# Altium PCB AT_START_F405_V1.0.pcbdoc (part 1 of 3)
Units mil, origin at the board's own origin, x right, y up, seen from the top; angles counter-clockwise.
Board outline 15424.54 x 3535.36 mil, 2 copper layers (Top Layer, Bottom Layer); 147 components, 139 nets, 556 pads, 794 vias.
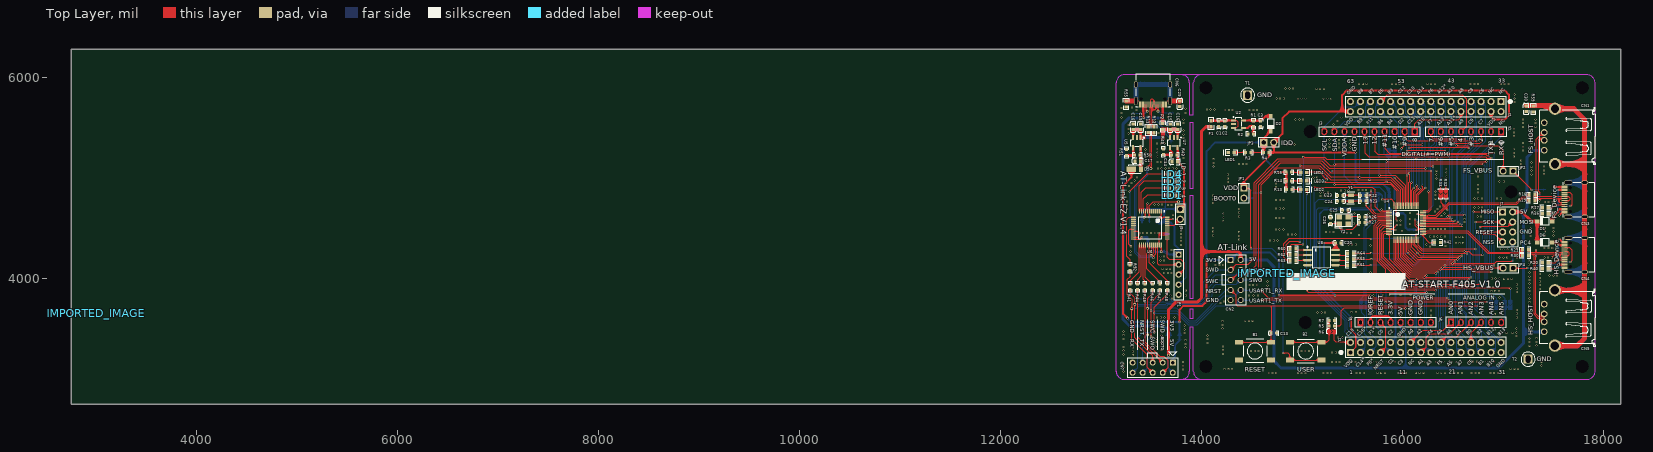
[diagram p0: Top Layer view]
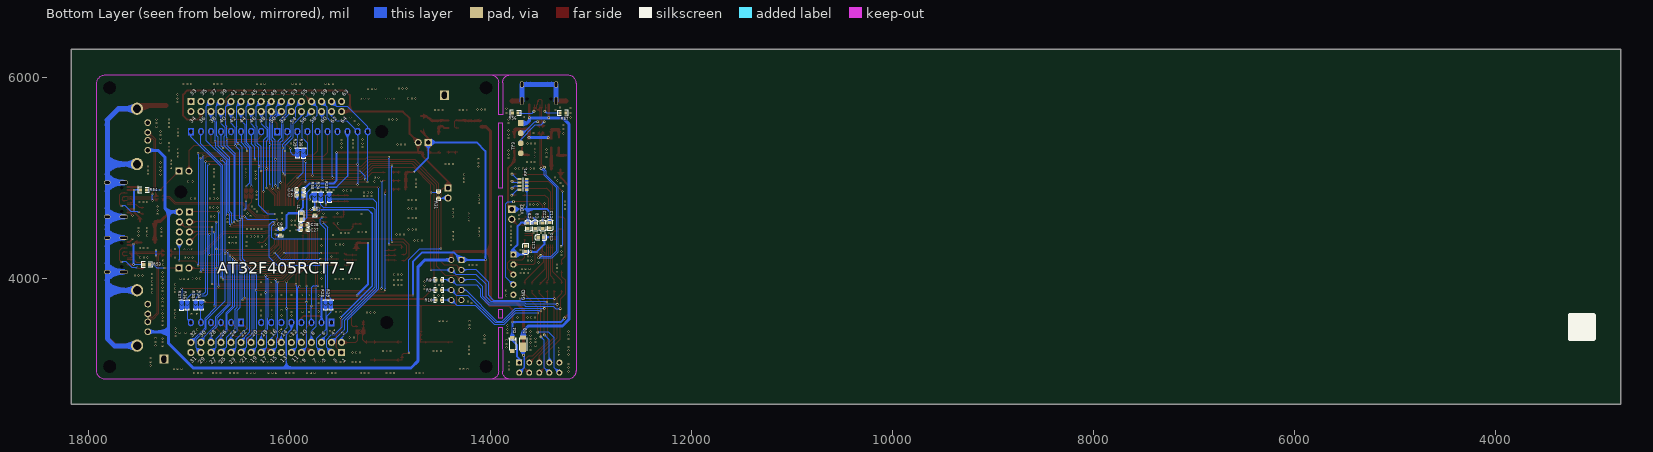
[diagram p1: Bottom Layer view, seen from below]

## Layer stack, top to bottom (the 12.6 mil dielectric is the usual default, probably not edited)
Top Layer: signal copper (thickness not stored)
Dielectric: dielectric 12.6, FR-4, Dk 4.8
Bottom Layer: signal copper (thickness not stored)

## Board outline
18174.54,2750 2750,2750 2750,6285.36 18174.54,6285.36
cut-out: 17855.2,5902.56 ccw(c17792.21,5902.56) 17729.21,5902.56 ccw(c17792.21,5902.56)
cut-out: 17854.57,3127.57 ccw(c17791.58,3127.57) 17728.58,3127.57 ccw(c17791.58,3127.57)
cut-out: 14107.57,3127.57 ccw(c14044.58,3127.57) 13981.58,3127.57 ccw(c14044.58,3127.57)
cut-out: 14107.57,5902.56 ccw(c14044.58,5902.56) 13981.58,5902.56 ccw(c14044.58,5902.56)
cut-out: 17146.57,4865.56 ccw(c17083.58,4865.56) 17020.58,4865.56 ccw(c17083.58,4865.56)
cut-out: 15096.57,3565.57 ccw(c15033.58,3565.57) 14970.58,3565.57 ccw(c15033.58,3565.57)
cut-out: 15146.57,5465.56 ccw(c15083.58,5465.56) 15020.58,5465.56 ccw(c15083.58,5465.56)

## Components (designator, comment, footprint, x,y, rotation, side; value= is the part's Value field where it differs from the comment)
B1 "BUTTON_SMT,6.0x6.0x4.5mm" BUTTON_SMT_6*6*5 14533.58,3280.57 r0 top
B2 "BUTTON_SMT,6.0x6.0x4.5mm" BUTTON_SMT_6*6*5 15038.58,3280.57 r180 top
C1 "10uF" 0603_C-M 14172.58,5544.37 r90 top
C2 "0.1uF" 0603_C-M 14232.58,5544.37 r90 top
C3 "10uF" 0603_C-M 14590.58,5544.37 r90 top
C4 "4.7uF" 0603_C-M 15896.58,4883.56 r180 bottom
C5 "0.1uF" 0603_C-M 15897.08,4833.56 r180 bottom
C6 "0.1uF" 0603_C-M 16091.58,4461.56 r90 bottom
C7 "0.1uF" 0603_C-M 15750.58,4662.56 r90 bottom
C8 "4.7uF" C0603 13556.58,4527.56 r270 bottom
C9 "CC0603KRX7R9BB104" C0603 13628.58,4527.56 r270 bottom
C10 "CC0603KRX7R9BB104" C0603 13498.58,4411.56 r0 bottom
C11 "CC0603KRX7R9BB104" C0603 13650.58,4299.56 r90 bottom
C12 "CC0603KRX7R9BB104" C0603 13410.58,4533.56 r270 bottom
C13 "0.1uF" 0603_C-M 14720.58,3459.57 r0 top
C14 "CL10A106KP8NNNC" C0603 13736.58,5164.56 r180 top
C15 "CL10A106KP8NNNC" C0603 13689.58,5514.56 r90 top
C16 "CC0603KRX7R9BB104" C0603 13764.58,5514.12 r90 top
C17 "CL10A106KP8NNNC" C0603 13367.58,5172.56 r180 top
C18 "CL10A106KP8NNNC" C0603 13319.58,5513.56 r90 top
C19 "CC0603KRX7R9BB104" C0603 13395.58,5513.12 r90 top
C20 "0.1uF" 0603_C-M 15363.02,4357 r0 top
C22 "CC0603KRX7R9BB104" C0603 13480.58,4529.56 r270 bottom
C23 "18pF" 0603_C-M 15383.58,4831.56 r180 top
C24 "18pF" 0603_C-M 15383.58,4772.56 r180 top
C25 "15pF" 0603_C-M 15433.08,4683.56 r180 top
C26 "15pF" 0603_C-M 15283.58,4576.06 r90 top
C27 "1uF" 0603_C-M 15857.08,4487.56 r180 bottom
C28 "0.1uF" 0603_C-M 15857.08,4536.56 r180 bottom
C29 "CC0603KRX7R9BB104" C0603 13784.58,5742.56 r90 top
C30 "CC0603KRX7R9BB104" C0603 17232.58,5692.01 r90 top
CN1 "USB type A" USB-A-TH__USB-AF-90 17466.58,5417.56 r90 top
CN2 "NC(Header 2x5)" HDR2X5#1 14290.92,4188.85 r270 top
CN3 "TYPEC-304-BCP16" USB-C-SMD_TYPEC-304-BCP16#1 17715.58,4788.56 r90 top
CN4 "TYPEC-304-BCP16" USB-C-SMD_TYPEC-304-BCP16#1 17715.58,4238.56 r90 top
CN5 "USB type A" USB-A-TH__USB-AF-90 17465.58,3610.57 r90 top
CN6 "TYPEC-304-BCP16" USB-C-SMD_TYPEC-304-BCP16#2 13518.58,5834.56 r180 top
CN7 "CON1" HDR2X5#2 13715.38,3165.97 r180 top
D1 "DFLS130L-7" SOD-123 17417.58,4572.56 r0 top
D2 "DFLS130L-7" SOD-123 14690.58,5544.36 r90 top
D3 "DFLS130L-7" POWERDI-123_L2.8-W1.8-LS3.7-RD 13676.62,3367.57 r90 bottom
D4 "SMF3.3A" SOD-123_L2.8-W1.8-LS3.7-RD 13782.58,3347.57 r270 bottom
D5 "DFLS130L-7" POWERDI-123_L2.8-W1.8-LS3.7-RD 13350.58,5090.56 r0 top
D6 "DFLS130L-7" SOD-123 17417.58,4363.56 r0 top
F1 "SMD0603B050TF" R0603#1 14096.58,5513.86 r90 top
F2 "SMD0603B050TF" R0603#2 13616.58,5517.56 r270 top
IMPORTED_IMAGE "IMPORTED_IMAGE" IMPORTED_IMAGE 3000,3658.57 r0 top
IMPORTED_IMAGE "IMPORTED_IMAGE" IMPORTED_IMAGE 14848.52,4055 r0 top
J1 "Header 2x16" HDR-M-2.54_2X16 16233.44,5714.86 r180 top
J2 "Header 2x16" HDR-M-2.54_2X16 16233.88,3317.14 r0 top
J3 "CON10" "FEMALE HEADER 1X10" 16123.87,5465.56 r180 top
J4 "CON8" "FEMALE HEADER 1X8" 15583.87,3565.56 r0 top
J5 "CON8" "FEMALE HEADER 1X8" 16983.87,5465.56 r180 top
J6 "CON6" "FEMALE HEADER 1X6" 16483.87,3565.57 r0 top
J7 "Header 4X2" HDR2X4 16998.88,4666.16 r270 top
J9 "1X2P,Male,DIP_2.54" HDR1X2 13789.38,4692.97 r270 top
JP1 "NC(Header 1x2)" "HEADER 1X2" 14423.58,4903.56 r270 top
JP2 "NC(Header 1x2)" "HEADER 1X2" 17103.58,5072.56 r180 top
JP3 "NC(Header 1x2)" "HEADER 1X2" 14620.58,5357.56 r0 top
JP4 "NC(Header 1x2)" "HEADER 1X2" 17103.58,4107.56 r180 top
L1 "0.5A,600R@100Mhz" 0603_L 15884.58,4622.56 r270 bottom
LD1 "RED" LED0603 13742.58,4832.77 r180 top
LD2 "GREEN" LED0603 13742.58,4902.37 r180 top
LD3 "BLUE" LED0603 13742.58,4971.97 r180 top
LD4 "YELLOW" LED0603 13742.58,5041.56 r180 top
LED1 "RED" LED0603 14328.58,5258.56 r180 top
LED2 "RED" LED0603 14988.58,4889.56 r0 top
LED3 "YELLOW" LED0603 14988.58,4975.56 r0 top
LED4 "GREEN" LED0603 14988.58,5059.56 r0 top
P1 "HDR-M-2.54_1x5" HDR-M-2.54_1X5 13772.58,4041.57 r270 top
R1 "51k" 0603_R-M 14518.58,5544.37 r270 top
R2 "15k" 0603_R-M 14490.58,5443.56 r180 top
R3 "1K" 0603_R-M 14466.58,5258.56 r0 top
R4 "0R" 0603_R-M 14647.58,5257.56 r0 top
R5 "0R" 0603_R-M 15296.58,3529.57 r0 top
R6 "NC" SB-PAD 15296.58,3473.57 r0 top
R7 "100K" 0603_R-M 15296.58,3585.57 r180 top
R8 "470R" 0603_R-M 14518.27,3989.76 r0 bottom
R9 "470R" 0603_R-M 14518.27,3887.76 r0 bottom
R10 "470R" 0603_R-M 14518.27,3789.76 r0 bottom
R11 "0603WAF0000T5E" R0603#2 13469.58,5484.9 r270 top
R12 "0603WAF0000T5E" R0603#2 13528.58,5484.56 r270 top
R13 "1K" 0603_R-M 14872.58,4889.56 r0 top
R14 "1K" 0603_R-M 14871.19,4975.21 r0 top
R15 "1K" 0603_R-M 14871.19,5061.21 r0 top
R16 "0603WAF5101T5E" R0603#2 17423.58,4646.56 r180 top
R17 "0603WAF5101T5E" R0603#2 17422.58,4706.56 r180 top
R18 "0603WAF220JT5E" R0603#2 17291.92,4837.56 r0 top
R19 "0603WAF220JT5E" R0603#2 17291.58,4778.56 r0 top
R20 "0603WAF5101T5E" R0603#2 17423.58,4160.56 r180 top
R21 "0603WAF220JT5E" R0603#2 17225.92,4287.56 r0 top
R22 "0R" 0603_R-M 15609.58,4831.56 r0 top
R23 "0R" 0603_R-M 15611.58,4773.56 r0 top
R24 "NC" SB-PAD 15689.58,4814.56 r270 bottom
R25 "NC" SB-PAD 15605.58,4814.56 r270 bottom
R26 "0R" 0603_R-M 15600.58,4615.56 r0 top
R27 "0R" 0603_R-M 15600.58,4561.56 r0 top
R28 "NC" SB-PAD 15643.58,3741.57 r270 bottom
R29 "NC" SB-PAD 15589.58,3742.57 r270 bottom
R30 "0603WAF220JT5E" R0603#2 17225.92,4228.56 r0 top
R31 "10K" 0603_R-M 14519.52,4831 r270 bottom
R32 "NC" SB-PAD 16433.58,4847.44 r270 top
R33 "NC" SB-PAD 16380.58,4847.85 r270 top
R34 "0R" SB-PAD 16880.58,3741.45 r270 bottom
R35 "NC" SB-PAD 16936.58,3740.96 r270 bottom
R36 "NC" SB-PAD 17020.58,3740.45 r270 bottom
R37 "0R" SB-PAD 17076.58,3739.84 r270 bottom
R38 "NC" SB-PAD 15864.58,5252.93 r270 bottom
R39 "0R" SB-PAD 15924.58,5253.56 r270 bottom
R40 "0603WAF5101T5E" R0603#2 17422.92,4100.56 r180 top
R41 "33R" 0603_R-M 13290.58,3919.57 r270 top
R42 "0603WAD1202T5E" R0603#2 16350.27,4361.56 r0 top
R43 "47K" 0603_R-M 13730.42,5235.02 r180 top
R44 "33R" 0603_R-M 13364.58,3919.57 r270 top
R45 "33R" 0603_R-M 13436.58,3919.57 r270 top
R46 "33R" 0603_R-M 13514.58,3921.57 r270 top
R47 "33R" 0603_R-M 13586.58,3923.57 r270 top
R48 "33R" 0603_R-M 13660.58,3919.57 r270 top
R49 "15K" 0603_R-M 13620.58,5263.56 r270 top
R50 "51K" 0603_R-M 13362.58,5232.56 r180 top
R51 "15K" 0603_R-M 13254.58,5257.56 r270 top
R52 "33R" 0603_R-M 13288.58,4109.56 r270 top
R53 "0603WAF1002T5E" R0603#2 17422.58,4141.56 r0 bottom
R54 "0603WAF1002T5E" R0603#2 17455.92,4884.56 r0 bottom
R55 "RC0603FR-071ML" R0603#2 13250.58,5740.9 r270 top
R56 "0603WAF5101T5E" R0603#2 13755.58,5650.56 r0 bottom
R57 "0603WAF5101T5E" R0603#2 13279.58,5650.56 r180 bottom
R58 "0R" SB-PAD 15750.58,4816.56 r270 bottom
R59 "RC0603FR-071ML" R0603#2 17302.58,5690.9 r270 top
R60 "0603WAF330JT5E" R0603#2 14911.86,4299 r0 top
R61 "0603WAF330JT5E" R0603#2 15484.18,4136 r180 top
R62 "0603WAF330JT5E" R0603#2 14911.86,4239 r0 top
R63 "0603WAF330JT5E" R0603#2 14911.86,4180 r0 top
R64 "0603WAF330JT5E" R0603#2 15484.18,4255 r180 top
R65 "0603WAF330JT5E" R0603#2 15484.18,4195.5 r180 top
RP1 "1K" 0603*4,8P4R 13640.58,4886.56 r90 bottom
T1 "Testpoint" TESTHOOK 14460.58,5827.56 r270 top
T2 "Testpoint" TESTHOOK 17252.58,3200.57 r90 top
TP3 "1X4P_2.54F" "HDR1X4 - TOP" 13699.93,5550.02 r90 bottom
U2 "RT9080N-08GJ5" SOT-23-5 14382.58,5476.54 r0 top
U4 "AT32F405RCT7-7" IC_LQFP64_7X7 16037.58,4558.56 r0 top
U5 "RT9080N-08GJ5" SOT-23-5 13295.14,5339.91 r270 top
U6 "AT32F403ACCT7" "LQFP48 - 2" 13600.09,4672.02 r270 top
U7 "RT9080N-08GJ5" SOT-23-5 13664.35,5341.91 r270 top
U8 "EN25QH128A-104HIP2T" SOP-8_L5.3-W5.3-P1.27-LS8.0-BL 15195.52,4212 r270 top
Y1 "32.768KHz" "XTAL_SOP - FC-12M" 15487.58,4831.56 r270 top
Y2 "CJ13-120001210B20" CRYSTAL-SMD_4P-L3.2-W2.5-BL 15416.58,4582.56 r0 top

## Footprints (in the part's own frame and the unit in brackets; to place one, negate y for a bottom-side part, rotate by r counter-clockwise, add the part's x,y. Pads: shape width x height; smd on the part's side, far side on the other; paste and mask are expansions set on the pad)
0603*4,8P4R [mm]
  rect 0.55x0.95 smd paste+0 mask+0.102: 1(0,0) 4(2.7,0) 5(2.7,1.85) 8(0,1.85)
  rect 0.5x0.95 smd paste+0 mask+0.102: 2(0.9,0) 3(1.8,0) 6(1.8,1.85) 7(0.9,1.85)
  silkscreen extent -0.43,0.94 3.1,0.94
0603_C-M [mil]
  rect 30x30 smd paste+0 mask+4: 1(27.5,0) 2(-27.5,0)
  silkscreen extent -50,-21 50,21
0603_L [mm]
  rect 0.93x0.9 smd paste+0 mask+0.102: 1(-0.77,0) 2(0.77,0)
  silkscreen extent -1.4,-0.64 1.4,0.64
0603_R-M [mil]
  rect 30x30 smd paste+0 mask+4: 1(27.5,0) 2(-27.5,0)
  silkscreen extent -50,-21 50,21
BUTTON_SMT_6*6*5 [mm]
  rect 2x1.2 smd paste+0 mask+0.102: 1(-4,2.25) 2(4,2.25) 3(-4,-2.25) 4(4,-2.25)
  silkscreen extent -3,-3 3,3
C0603 [mm]
  rect 0.8x0.9 smd paste+0 mask+0.051: 1(-0.7,0) 2(0.7,0)
  silkscreen extent -1.41,-0.71 1.39,0.72
CRYSTAL-SMD_4P-L3.2-W2.5-BL [mm]
  rect 1.4x1.2 smd paste+0 mask+0.051: 1(-1.1,-0.85) 2(1.1,-0.85) 3(1.1,0.85) 4(-1.1,0.85)
  silkscreen extent -2.26,-1.91 2.03,1.68
"FEMALE HEADER 1X6" [mm]
  oval 1x0.7 hole 0.7 slot 1 at 90 deg: 1(0,0) 2(2.54,0) 3(5.08,0) 4(7.62,0) 5(10.16,0) 6(12.7,0)
  Top Layer region: 13.4,-0.2 13.306,-0.55 13.05,-0.806 12.7,-0.9 12.35,-0.806 12.094,-0.55 12,-0.2 12,0.2 12.094,0.55 12.35,0.806 12.7,0.9 13.05,0.806 13.306,0.55 13.4,0.2
  Top Layer region: 10.86,-0.2 10.766,-0.55 10.51,-0.806 10.16,-0.9 9.81,-0.806 9.554,-0.55 9.46,-0.2 9.46,0.2 9.554,0.55 9.81,0.806 10.16,0.9 10.51,0.806 10.766,0.55 10.86,0.2
  Top Layer region: 8.32,-0.2 8.226,-0.55 7.97,-0.806 7.62,-0.9 7.27,-0.806 7.014,-0.55 6.92,-0.2 6.92,0.2 7.014,0.55 7.27,0.806 7.62,0.9 7.97,0.806 8.226,0.55 8.32,0.2
  Top Layer region: 5.78,-0.2 5.686,-0.55 5.43,-0.806 5.08,-0.9 4.73,-0.806 4.474,-0.55 4.38,-0.2 4.38,0.2 4.474,0.55 4.73,0.806 5.08,0.9 5.43,0.806 5.686,0.55 5.78,0.2
  Top Layer region: 3.24,-0.2 3.146,-0.55 2.89,-0.806 2.54,-0.9 2.19,-0.806 1.934,-0.55 1.84,-0.2 1.84,0.2 1.934,0.55 2.19,0.806 2.54,0.9 2.89,0.806 3.146,0.55 3.24,0.2
  Top Layer region: -0.7,0.9 0.7,0.9 0.7,-0.9 -0.7,-0.9
  Bottom Layer region: 13.4,-0.2 13.306,-0.55 13.05,-0.806 12.7,-0.9 12.35,-0.806 12.094,-0.55 12,-0.2 12,0.2 12.094,0.55 12.35,0.806 12.7,0.9 13.05,0.806 13.306,0.55 13.4,0.2
  Bottom Layer region: 10.86,-0.2 10.766,-0.55 10.51,-0.806 10.16,-0.9 9.81,-0.806 9.554,-0.55 9.46,-0.2 9.46,0.2 9.554,0.55 9.81,0.806 10.16,0.9 10.51,0.806 10.766,0.55 10.86,0.2
  Bottom Layer region: 8.32,-0.2 8.226,-0.55 7.97,-0.806 7.62,-0.9 7.27,-0.806 7.014,-0.55 6.92,-0.2 6.92,0.2 7.014,0.55 7.27,0.806 7.62,0.9 7.97,0.806 8.226,0.55 8.32,0.2
  Bottom Layer region: 5.78,-0.2 5.686,-0.55 5.43,-0.806 5.08,-0.9 4.73,-0.806 4.474,-0.55 4.38,-0.2 4.38,0.2 4.474,0.55 4.73,0.806 5.08,0.9 5.43,0.806 5.686,0.55 5.78,0.2
  Bottom Layer region: 3.24,-0.2 3.146,-0.55 2.89,-0.806 2.54,-0.9 2.19,-0.806 1.934,-0.55 1.84,-0.2 1.84,0.2 1.934,0.55 2.19,0.806 2.54,0.9 2.89,0.806 3.146,0.55 3.24,0.2
  Bottom Layer region: -0.7,0.9 0.7,0.9 0.7,-0.9 -0.7,-0.9
  Multi-Layer region: 13.4,-0.2 13.306,-0.55 13.05,-0.806 12.7,-0.9 12.35,-0.806 12.094,-0.55 12,-0.2 12,0.2 12.094,0.55 12.35,0.806 12.7,0.9 13.05,0.806 13.306,0.55 13.4,0.2
  Multi-Layer region: 10.86,-0.2 10.766,-0.55 10.51,-0.806 10.16,-0.9 9.81,-0.806 9.554,-0.55 9.46,-0.2 9.46,0.2 9.554,0.55 9.81,0.806 10.16,0.9 10.51,0.806 10.766,0.55 10.86,0.2
  Multi-Layer region: 8.32,-0.2 8.226,-0.55 7.97,-0.806 7.62,-0.9 7.27,-0.806 7.014,-0.55 6.92,-0.2 6.92,0.2 7.014,0.55 7.27,0.806 7.62,0.9 7.97,0.806 8.226,0.55 8.32,0.2
  Multi-Layer region: 5.78,-0.2 5.686,-0.55 5.43,-0.806 5.08,-0.9 4.73,-0.806 4.474,-0.55 4.38,-0.2 4.38,0.2 4.474,0.55 4.73,0.806 5.08,0.9 5.43,0.806 5.686,0.55 5.78,0.2
  Multi-Layer region: 3.24,-0.2 3.146,-0.55 2.89,-0.806 2.54,-0.9 2.19,-0.806 1.934,-0.55 1.84,-0.2 1.84,0.2 1.934,0.55 2.19,0.806 2.54,0.9 2.89,0.806 3.146,0.55 3.24,0.2
  Multi-Layer region: -0.7,0.9 0.7,0.9 0.7,-0.9 -0.7,-0.9
  silkscreen extent -1.27,-1.17 13.97,1.27
"FEMALE HEADER 1X8" [mm]
  oval 1x0.7 hole 0.7 slot 1 at 90 deg: 1(0,0) 2(2.54,0) 3(5.08,0) 4(7.62,0) 5(10.16,0) 6(12.7,0) 7(15.24,0) 8(17.78,0)
  Top Layer region: -0.7,0.9 0.7,0.9 0.7,-0.9 -0.7,-0.9
  Top Layer region: 3.24,-0.2 3.146,-0.55 2.89,-0.806 2.54,-0.9 2.19,-0.806 1.934,-0.55 1.84,-0.2 1.84,0.2 1.934,0.55 2.19,0.806 2.54,0.9 2.89,0.806 3.146,0.55 3.24,0.2
  Top Layer region: 5.78,-0.2 5.686,-0.55 5.43,-0.806 5.08,-0.9 4.73,-0.806 4.474,-0.55 4.38,-0.2 4.38,0.2 4.474,0.55 4.73,0.806 5.08,0.9 5.43,0.806 5.686,0.55 5.78,0.2
  Top Layer region: 8.32,-0.2 8.226,-0.55 7.97,-0.806 7.62,-0.9 7.27,-0.806 7.014,-0.55 6.92,-0.2 6.92,0.2 7.014,0.55 7.27,0.806 7.62,0.9 7.97,0.806 8.226,0.55 8.32,0.2
  Top Layer region: 10.86,-0.2 10.766,-0.55 10.51,-0.806 10.16,-0.9 9.81,-0.806 9.554,-0.55 9.46,-0.2 9.46,0.2 9.554,0.55 9.81,0.806 10.16,0.9 10.51,0.806 10.766,0.55 10.86,0.2
  Top Layer region: 13.4,-0.2 13.306,-0.55 13.05,-0.806 12.7,-0.9 12.35,-0.806 12.094,-0.55 12,-0.2 12,0.2 12.094,0.55 12.35,0.806 12.7,0.9 13.05,0.806 13.306,0.55 13.4,0.2
  Top Layer region: 15.94,-0.2 15.846,-0.55 15.59,-0.806 15.24,-0.9 14.89,-0.806 14.634,-0.55 14.54,-0.2 14.54,0.2 14.634,0.55 14.89,0.806 15.24,0.9 15.59,0.806 15.846,0.55 15.94,0.2
  Top Layer region: 18.48,-0.2 18.386,-0.55 18.13,-0.806 17.78,-0.9 17.43,-0.806 17.174,-0.55 17.08,-0.2 17.08,0.2 17.174,0.55 17.43,0.806 17.78,0.9 18.13,0.806 18.386,0.55 18.48,0.2
  Bottom Layer region: -0.7,0.9 0.7,0.9 0.7,-0.9 -0.7,-0.9
  Bottom Layer region: 3.24,-0.2 3.146,-0.55 2.89,-0.806 2.54,-0.9 2.19,-0.806 1.934,-0.55 1.84,-0.2 1.84,0.2 1.934,0.55 2.19,0.806 2.54,0.9 2.89,0.806 3.146,0.55 3.24,0.2
  Bottom Layer region: 5.78,-0.2 5.686,-0.55 5.43,-0.806 5.08,-0.9 4.73,-0.806 4.474,-0.55 4.38,-0.2 4.38,0.2 4.474,0.55 4.73,0.806 5.08,0.9 5.43,0.806 5.686,0.55 5.78,0.2
  Bottom Layer region: 8.32,-0.2 8.226,-0.55 7.97,-0.806 7.62,-0.9 7.27,-0.806 7.014,-0.55 6.92,-0.2 6.92,0.2 7.014,0.55 7.27,0.806 7.62,0.9 7.97,0.806 8.226,0.55 8.32,0.2
  Bottom Layer region: 10.86,-0.2 10.766,-0.55 10.51,-0.806 10.16,-0.9 9.81,-0.806 9.554,-0.55 9.46,-0.2 9.46,0.2 9.554,0.55 9.81,0.806 10.16,0.9 10.51,0.806 10.766,0.55 10.86,0.2
  Bottom Layer region: 13.4,-0.2 13.306,-0.55 13.05,-0.806 12.7,-0.9 12.35,-0.806 12.094,-0.55 12,-0.2 12,0.2 12.094,0.55 12.35,0.806 12.7,0.9 13.05,0.806 13.306,0.55 13.4,0.2
  Bottom Layer region: 15.94,-0.2 15.846,-0.55 15.59,-0.806 15.24,-0.9 14.89,-0.806 14.634,-0.55 14.54,-0.2 14.54,0.2 14.634,0.55 14.89,0.806 15.24,0.9 15.59,0.806 15.846,0.55 15.94,0.2
  Bottom Layer region: 18.48,-0.2 18.386,-0.55 18.13,-0.806 17.78,-0.9 17.43,-0.806 17.174,-0.55 17.08,-0.2 17.08,0.2 17.174,0.55 17.43,0.806 17.78,0.9 18.13,0.806 18.386,0.55 18.48,0.2
  Multi-Layer region: -0.7,0.9 0.7,0.9 0.7,-0.9 -0.7,-0.9
  Multi-Layer region: 3.24,-0.2 3.146,-0.55 2.89,-0.806 2.54,-0.9 2.19,-0.806 1.934,-0.55 1.84,-0.2 1.84,0.2 1.934,0.55 2.19,0.806 2.54,0.9 2.89,0.806 3.146,0.55 3.24,0.2
  Multi-Layer region: 5.78,-0.2 5.686,-0.55 5.43,-0.806 5.08,-0.9 4.73,-0.806 4.474,-0.55 4.38,-0.2 4.38,0.2 4.474,0.55 4.73,0.806 5.08,0.9 5.43,0.806 5.686,0.55 5.78,0.2
  Multi-Layer region: 8.32,-0.2 8.226,-0.55 7.97,-0.806 7.62,-0.9 7.27,-0.806 7.014,-0.55 6.92,-0.2 6.92,0.2 7.014,0.55 7.27,0.806 7.62,0.9 7.97,0.806 8.226,0.55 8.32,0.2
  Multi-Layer region: 10.86,-0.2 10.766,-0.55 10.51,-0.806 10.16,-0.9 9.81,-0.806 9.554,-0.55 9.46,-0.2 9.46,0.2 9.554,0.55 9.81,0.806 10.16,0.9 10.51,0.806 10.766,0.55 10.86,0.2
  Multi-Layer region: 13.4,-0.2 13.306,-0.55 13.05,-0.806 12.7,-0.9 12.35,-0.806 12.094,-0.55 12,-0.2 12,0.2 12.094,0.55 12.35,0.806 12.7,0.9 13.05,0.806 13.306,0.55 13.4,0.2
  Multi-Layer region: 15.94,-0.2 15.846,-0.55 15.59,-0.806 15.24,-0.9 14.89,-0.806 14.634,-0.55 14.54,-0.2 14.54,0.2 14.634,0.55 14.89,0.806 15.24,0.9 15.59,0.806 15.846,0.55 15.94,0.2
  Multi-Layer region: 18.48,-0.2 18.386,-0.55 18.13,-0.806 17.78,-0.9 17.43,-0.806 17.174,-0.55 17.08,-0.2 17.08,0.2 17.174,0.55 17.43,0.806 17.78,0.9 18.13,0.806 18.386,0.55 18.48,0.2
  silkscreen extent -1.27,-1.17 19.05,1.27
"FEMALE HEADER 1X10" [mm]
  oval 1x0.7 hole 0.7 slot 1 at 90 deg: 1(0,0) 2(2.54,0) 3(5.08,0) 4(7.62,0) 5(10.16,0) 6(12.7,0) 7(15.24,0) 8(17.78,0) 9(20.32,0) 10(22.86,0)
  Top Layer region: 23.56,-0.2 23.466,-0.55 23.21,-0.806 22.86,-0.9 22.51,-0.806 22.254,-0.55 22.16,-0.2 22.16,0.2 22.254,0.55 22.51,0.806 22.86,0.9 23.21,0.806 23.466,0.55 23.56,0.2
  Top Layer region: 21.02,-0.2 20.926,-0.55 20.67,-0.806 20.32,-0.9 19.97,-0.806 19.714,-0.55 19.62,-0.2 19.62,0.2 19.714,0.55 19.97,0.806 20.32,0.9 20.67,0.806 20.926,0.55 21.02,0.2
  Top Layer region: 18.48,-0.2 18.386,-0.55 18.13,-0.806 17.78,-0.9 17.43,-0.806 17.174,-0.55 17.08,-0.2 17.08,0.2 17.174,0.55 17.43,0.806 17.78,0.9 18.13,0.806 18.386,0.55 18.48,0.2
  Top Layer region: 15.94,-0.2 15.846,-0.55 15.59,-0.806 15.24,-0.9 14.89,-0.806 14.634,-0.55 14.54,-0.2 14.54,0.2 14.634,0.55 14.89,0.806 15.24,0.9 15.59,0.806 15.846,0.55 15.94,0.2
  Top Layer region: 13.4,-0.2 13.306,-0.55 13.05,-0.806 12.7,-0.9 12.35,-0.806 12.094,-0.55 12,-0.2 12,0.2 12.094,0.55 12.35,0.806 12.7,0.9 13.05,0.806 13.306,0.55 13.4,0.2
  Top Layer region: 10.86,-0.2 10.766,-0.55 10.51,-0.806 10.16,-0.9 9.81,-0.806 9.554,-0.55 9.46,-0.2 9.46,0.2 9.554,0.55 9.81,0.806 10.16,0.9 10.51,0.806 10.766,0.55 10.86,0.2
  Top Layer region: 8.32,-0.2 8.226,-0.55 7.97,-0.806 7.62,-0.9 7.27,-0.806 7.014,-0.55 6.92,-0.2 6.92,0.2 7.014,0.55 7.27,0.806 7.62,0.9 7.97,0.806 8.226,0.55 8.32,0.2
  Top Layer region: 5.78,-0.2 5.686,-0.55 5.43,-0.806 5.08,-0.9 4.73,-0.806 4.474,-0.55 4.38,-0.2 4.38,0.2 4.474,0.55 4.73,0.806 5.08,0.9 5.43,0.806 5.686,0.55 5.78,0.2
  Top Layer region: 3.24,-0.2 3.146,-0.55 2.89,-0.806 2.54,-0.9 2.19,-0.806 1.934,-0.55 1.84,-0.2 1.84,0.2 1.934,0.55 2.19,0.806 2.54,0.9 2.89,0.806 3.146,0.55 3.24,0.2
  Top Layer region: -0.7,0.9 0.7,0.9 0.7,-0.9 -0.7,-0.9
  Bottom Layer region: 23.56,-0.2 23.466,-0.55 23.21,-0.806 22.86,-0.9 22.51,-0.806 22.254,-0.55 22.16,-0.2 22.16,0.2 22.254,0.55 22.51,0.806 22.86,0.9 23.21,0.806 23.466,0.55 23.56,0.2
  Bottom Layer region: 21.02,-0.2 20.926,-0.55 20.67,-0.806 20.32,-0.9 19.97,-0.806 19.714,-0.55 19.62,-0.2 19.62,0.2 19.714,0.55 19.97,0.806 20.32,0.9 20.67,0.806 20.926,0.55 21.02,0.2
  Bottom Layer region: 18.48,-0.2 18.386,-0.55 18.13,-0.806 17.78,-0.9 17.43,-0.806 17.174,-0.55 17.08,-0.2 17.08,0.2 17.174,0.55 17.43,0.806 17.78,0.9 18.13,0.806 18.386,0.55 18.48,0.2
  Bottom Layer region: 15.94,-0.2 15.846,-0.55 15.59,-0.806 15.24,-0.9 14.89,-0.806 14.634,-0.55 14.54,-0.2 14.54,0.2 14.634,0.55 14.89,0.806 15.24,0.9 15.59,0.806 15.846,0.55 15.94,0.2
  Bottom Layer region: 13.4,-0.2 13.306,-0.55 13.05,-0.806 12.7,-0.9 12.35,-0.806 12.094,-0.55 12,-0.2 12,0.2 12.094,0.55 12.35,0.806 12.7,0.9 13.05,0.806 13.306,0.55 13.4,0.2
  Bottom Layer region: 10.86,-0.2 10.766,-0.55 10.51,-0.806 10.16,-0.9 9.81,-0.806 9.554,-0.55 9.46,-0.2 9.46,0.2 9.554,0.55 9.81,0.806 10.16,0.9 10.51,0.806 10.766,0.55 10.86,0.2
  Bottom Layer region: 8.32,-0.2 8.226,-0.55 7.97,-0.806 7.62,-0.9 7.27,-0.806 7.014,-0.55 6.92,-0.2 6.92,0.2 7.014,0.55 7.27,0.806 7.62,0.9 7.97,0.806 8.226,0.55 8.32,0.2
  Bottom Layer region: 5.78,-0.2 5.686,-0.55 5.43,-0.806 5.08,-0.9 4.73,-0.806 4.474,-0.55 4.38,-0.2 4.38,0.2 4.474,0.55 4.73,0.806 5.08,0.9 5.43,0.806 5.686,0.55 5.78,0.2
  Bottom Layer region: 3.24,-0.2 3.146,-0.55 2.89,-0.806 2.54,-0.9 2.19,-0.806 1.934,-0.55 1.84,-0.2 1.84,0.2 1.934,0.55 2.19,0.806 2.54,0.9 2.89,0.806 3.146,0.55 3.24,0.2
  Bottom Layer region: -0.7,0.9 0.7,0.9 0.7,-0.9 -0.7,-0.9
  Multi-Layer region: 23.56,-0.2 23.466,-0.55 23.21,-0.806 22.86,-0.9 22.51,-0.806 22.254,-0.55 22.16,-0.2 22.16,0.2 22.254,0.55 22.51,0.806 22.86,0.9 23.21,0.806 23.466,0.55 23.56,0.2
  Multi-Layer region: 21.02,-0.2 20.926,-0.55 20.67,-0.806 20.32,-0.9 19.97,-0.806 19.714,-0.55 19.62,-0.2 19.62,0.2 19.714,0.55 19.97,0.806 20.32,0.9 20.67,0.806 20.926,0.55 21.02,0.2
  Multi-Layer region: 18.48,-0.2 18.386,-0.55 18.13,-0.806 17.78,-0.9 17.43,-0.806 17.174,-0.55 17.08,-0.2 17.08,0.2 17.174,0.55 17.43,0.806 17.78,0.9 18.13,0.806 18.386,0.55 18.48,0.2
  Multi-Layer region: 15.94,-0.2 15.846,-0.55 15.59,-0.806 15.24,-0.9 14.89,-0.806 14.634,-0.55 14.54,-0.2 14.54,0.2 14.634,0.55 14.89,0.806 15.24,0.9 15.59,0.806 15.846,0.55 15.94,0.2
  Multi-Layer region: 13.4,-0.2 13.306,-0.55 13.05,-0.806 12.7,-0.9 12.35,-0.806 12.094,-0.55 12,-0.2 12,0.2 12.094,0.55 12.35,0.806 12.7,0.9 13.05,0.806 13.306,0.55 13.4,0.2
  Multi-Layer region: 10.86,-0.2 10.766,-0.55 10.51,-0.806 10.16,-0.9 9.81,-0.806 9.554,-0.55 9.46,-0.2 9.46,0.2 9.554,0.55 9.81,0.806 10.16,0.9 10.51,0.806 10.766,0.55 10.86,0.2
  Multi-Layer region: 8.32,-0.2 8.226,-0.55 7.97,-0.806 7.62,-0.9 7.27,-0.806 7.014,-0.55 6.92,-0.2 6.92,0.2 7.014,0.55 7.27,0.806 7.62,0.9 7.97,0.806 8.226,0.55 8.32,0.2
  Multi-Layer region: 5.78,-0.2 5.686,-0.55 5.43,-0.806 5.08,-0.9 4.73,-0.806 4.474,-0.55 4.38,-0.2 4.38,0.2 4.474,0.55 4.73,0.806 5.08,0.9 5.43,0.806 5.686,0.55 5.78,0.2
  Multi-Layer region: 3.24,-0.2 3.146,-0.55 2.89,-0.806 2.54,-0.9 2.19,-0.806 1.934,-0.55 1.84,-0.2 1.84,0.2 1.934,0.55 2.19,0.806 2.54,0.9 2.89,0.806 3.146,0.55 3.24,0.2
  Multi-Layer region: -0.7,0.9 0.7,0.9 0.7,-0.9 -0.7,-0.9
  silkscreen extent -1.27,-1.17 24.1,1.27
HDR1X2 [mm]
  rect 1.8x1.8 hole 1 slot 1.005 at 0 deg paste+0 mask+0.051: 1(0,0)
  round 1.8 hole 1 slot 1.005 at 0 deg paste+0 mask+0.051: 2(2.54,0)
  silkscreen extent -1.27,-1.27 3.81,1.27
"HDR1X4 - TOP" [mm]
  rect 1.5x1.5 smd paste+0 mask+0.102: 1(0,0)
  round 1.5 smd paste+0 mask+0.102: 2(-2.54,0) 3(-5.08,0) 4(-7.62,0)
HDR2X4 [mm]
  rect 1.8x1.8 hole 1 paste+0 mask+0.102: 1(0,0)
  round 1.8 hole 1 paste+0 mask+0.102: 2(0,2.54) 3(2.54,0) 4(2.54,2.54) 5(5.08,0) 6(5.08,2.54) 7(7.62,0) 8(7.62,2.54)
  silkscreen extent -1.27,-1.27 8.89,3.81
HDR2X5#1 [mm]
  rect 1.5x1.5 hole 0.9 slot 0.905 at 0 deg paste+0 mask+0.051: 1(0,0)
  round 1.5 hole 0.9 slot 0.905 at 0 deg paste+0 mask+0.051: 2(0,2.54) 3(2.54,0) 4(2.54,2.54) 5(5.08,0) 6(5.08,2.54) 7(7.62,0) 8(7.62,2.54) 9(10.16,0) 10(10.16,2.54)
  silkscreen extent -1.27,-1.27 11.43,3.81
HDR2X5#2 [mm]
  rect 1.5x1.5 hole 0.9 paste+0 mask+0.102: 1(0,0)
  round 1.5 hole 0.9 paste+0 mask+0.102: 2(0,2.54) 3(2.54,0) 4(2.54,2.54) 5(5.08,0) 6(5.08,2.54) 7(7.62,0) 8(7.62,2.54) 9(10.16,0) 10(10.16,2.54)
  silkscreen extent -1.27,-1.27 11.43,3.81
HDR-M-2.54_1X5 [mil]
  rect 62x62 hole 35 paste+0 mask+2: 1(-200,0)
  round 62 hole 35 paste+0 mask+2: 2(-100,0) 3(0,0) 4(100,0) 5(200,0)
  silkscreen extent -250,-50 250,50
HDR-M-2.54_2X16 [mm]
  rect 1.8x1.8 hole 1 paste+0 mask+0.051: 1(-19.05,-1.27)
  round 1.8 hole 1 paste+0 mask+0.051: 2(-19.05,1.27) 3(-16.51,-1.27) 4(-16.51,1.27) 5(-13.97,-1.27) 6(-13.97,1.27) 7(-11.43,-1.27) 8(-11.43,1.27) 9(-8.89,-1.27) 10(-8.89,1.27) 11(-6.35,-1.27) 12(-6.35,1.27) 13(-3.81,-1.27) 14(-3.81,1.27) 15(-1.27,-1.27) 16(-1.27,1.27) 17(1.27,-1.27) 18(1.27,1.27) 19(3.81,-1.27) 20(3.81,1.27) 21(6.35,-1.27) 22(6.35,1.27) 23(8.89,-1.27) 24(8.89,1.27) 25(11.43,-1.27) 26(11.43,1.27) 27(13.97,-1.27) 28(13.97,1.27) 29(16.51,-1.27) 30(16.51,1.27) 31(19.05,-1.27) 32(19.05,1.27)
  silkscreen extent -20.32,-2.54 20.32,2.54
"HEADER 1X2" [mm]
  rect 1.8x1.8 hole 1 slot 1.005 at 0 deg paste+0 mask+0.051: 1(0,0)
  round 1.8 hole 1 slot 1.005 at 0 deg paste+0 mask+0.051: 2(2.54,0)
  silkscreen extent -1.27,-1.27 3.81,1.27
IC_LQFP64_7X7 [mm]
  rect 1.6x0.25 smd paste+0 mask+0.102: 1(-4.3,3) 2(-4.3,2.6) 3(-4.3,2.2) 4(-4.3,1.8) 5(-4.3,1.4) 6(-4.3,1) 7(-4.3,0.6) 8(-4.3,0.2) 9(-4.3,-0.2) 10(-4.3,-0.6) 11(-4.3,-1) 12(-4.3,-1.4) 13(-4.3,-1.8) 14(-4.3,-2.2) 15(-4.3,-2.6) 16(-4.3,-3) 33(4.3,-3) 34(4.3,-2.6) 35(4.3,-2.2) 36(4.3,-1.8) 37(4.3,-1.4) 38(4.3,-1) 39(4.3,-0.6) 40(4.3,-0.2) 41(4.3,0.2) 42(4.3,0.6) 43(4.3,1) 44(4.3,1.4) 45(4.3,1.8) 46(4.3,2.2) 47(4.3,2.6) 48(4.3,3)
  rect 0.25x1.6 smd paste+0 mask+0.102: 17(-3,-4.3) 18(-2.6,-4.3) 19(-2.2,-4.3) 20(-1.8,-4.3) 21(-1.4,-4.3) 22(-1,-4.3) 23(-0.6,-4.3) 24(-0.2,-4.3) 25(0.2,-4.3) 26(0.6,-4.3) 27(1,-4.3) 28(1.4,-4.3) 29(1.8,-4.3) 30(2.2,-4.3) 31(2.6,-4.3) 32(3,-4.3) 49(3,4.3) 50(2.6,4.3) 51(2.2,4.3) 52(1.8,4.3) 53(1.4,4.3) 54(1,4.3) 55(0.6,4.3) 56(0.2,4.3) 57(-0.2,4.3) 58(-0.6,4.3) 59(-1,4.3) 60(-1.4,4.3) 61(-1.8,4.3) 62(-2.2,4.3) 63(-2.6,4.3) 64(-3,4.3)
  silkscreen extent -4.42,-3.1 3.1,3.82
IMPORTED_IMAGE [mil]
LED0603 [mil]
  rect 36x32 smd paste+0 mask+4: 1(-0.04,0.2) 2(60.96,0.2)
  silkscreen extent -28,-28 110,27
"LQFP48 - 2" [mm]
  rect 1.2x0.3 smd paste+0 mask+0.102: 1(0,0) 2(0,-0.5) 3(0,-1) 4(0,-1.5) 5(0,-2) 6(0,-2.5) 7(0,-3) 8(0,-3.5) 9(0,-4) 10(0,-4.5) 11(0,-5) 12(0,-5.5) 25(8.5,-5.5) 26(8.5,-5) 27(8.5,-4.5) 28(8.5,-4) 29(8.5,-3.5) 30(8.5,-3) 31(8.5,-2.5) 32(8.5,-2) 33(8.5,-1.5) 34(8.5,-1) 35(8.5,-0.5) 36(8.5,0)
  rect 0.3x1.2 smd paste+0 mask+0.102: 13(1.5,-7) 14(2,-7) 15(2.5,-7) 16(3,-7) 17(3.5,-7) 18(4,-7) 19(4.5,-7) 20(5,-7) 21(5.5,-7) 22(6,-7) 23(6.5,-7) 24(7,-7) 37(7,1.5) 38(6.5,1.5) 39(6,1.5) 40(5.5,1.5) 41(5,1.5) 42(4.5,1.5) 43(4,1.5) 44(3.5,1.5) 45(3,1.5) 46(2.5,1.5) 47(2,1.5) 48(1.5,1.5)
  silkscreen extent -0.12,-5.71 7.11,0.89
POWERDI-123_L2.8-W1.8-LS3.7-RD [mm]
  rect 2.4x1.5 smd paste+0 mask+0.051: 1(-1.187,0)
  rect 1.05x1.5 smd paste+0 mask+0.051: 2(1.187,0)
  silkscreen extent -2,-1 1.2,1
R0603#1 [mil]
  rect 36x32 smd paste+0 mask+4: 1(-0.04,0.2) 2(60.96,0.2)
  silkscreen extent -28,-27 89,27
R0603#2 [mil]
  rect 31.75x34.02 smd paste-3937.01 mask+2: 1(-29.66,0) 2(29.66,0)
  silkscreen extent -55,-26 55,26
SB-PAD [mil]
  Top Layer region: -47.24,-19.68 -47.24,19.68 -16.45,19.68 1,0 -17.05,-19.68
  Top Layer region: -4.69,19.68 15,0 -4.69,-19.69 47.24,-19.68 47.24,19.68
  silkscreen extent -50,-23 50,23
SOD-123 [mm]
  rect 1.2x1 smd paste+0 mask+0.102: 1(1.905,0) 2(-1.905,0)
  silkscreen extent -1.14,-0.89 1.14,0.89
SOD-123_L2.8-W1.8-LS3.7-RD [mm]
  rect 0.95x1.15 smd paste+0 mask+0.051: 1(-1.692,0) 2(1.692,0)
  silkscreen extent -1.63,-0.94 1.41,0.94
SOP-8_L5.3-W5.3-P1.27-LS8.0-BL [mil]
  oval 23.98x86.79 smd mask+2: 1(-75,-139.46) 2(-25,-139.46) 3(25,-139.46) 4(75,-139.46) 5(75,139.46) 6(25,139.46) 7(-25,139.46) 8(-75,139.46)
  silkscreen extent -111,-145 106,87
SOT-23-5 [mil]
  rect 50x20 smd paste+0 mask+4: 1(-65,100) 2(-65,63) 3(-65,25) 4(35,25) 5(35,100)
  silkscreen extent -65,1 18,135
TESTHOOK [mm]
  rect 2.3x2.3 hole 1.2 slot 1.8 at 0 deg paste+0 mask+0.102: 1(0,0)
  silkscreen extent -1.8,-1.8 1.8,1.8
USB-A-TH__USB-AF-90 [mm]
  round 1.7 hole 1.1 copper offset 0,0 paste+0 mask+0.051: 1(-3.5,1.355) 4(3.5,1.355)
  round 1.7 hole 1.1 paste+0 mask+0.051: 2(-1,1.355) 3(1,1.355)
  round 3.1 hole 2.1 paste+0 mask+0.051: SH1(7,-1.355) SH2(-7,-1.355)
  silkscreen extent -7.22,-11.51 7.22,2.49
USB-C-SMD_TYPEC-304-BCP16#1 [mil]
  oval 39.4x82.7 hole 23.6 slot 70.9 at 90 deg paste+0 mask+2: 13(-170.1,64.3) 14(170.1,64.3)
  oval 39.4x63 hole 23.6 slot 47.2 at 90 deg paste+0 mask+2: 15(-170.1,-100.3) 16(170.1,-100.3)
  rect 23.6x57.1 smd paste+0 mask+2: A1B12(-127,100.3) A4B9(-96.5,100.3) B1A12(126.8,100.3) B4A9(96.5,100.3)
  rect 11.8x57.1 smd paste+0 mask+2: A5(-49.2,100.3) A6(-9.8,100.3) A7(9.8,100.3) A8(49.2,100.3) B5(68.9,100.3) B6(29.5,100.3) B7(-29.5,100.3) B8(-68.9,100.3)
  Multi-Layer board cut-out: 117.3,29.6 123.29,30.97 128.09,34.8 130.75,40.33 130.75,46.47 128.09,52 123.29,55.83 117.3,57.2 117.3,57.2 111.31,55.83 106.51,52 103.85,46.47 103.85,40.33 106.51,34.8 111.31,30.97 117.3,29.6
  Multi-Layer board cut-out: -117.3,29.6 -111.31,30.97 -106.51,34.8 -103.85,40.33 -103.85,46.47 -106.51,52 -111.31,55.83 -117.3,57.2 -117.3,57.2 -123.29,55.83 -128.09,52 -130.75,46.47 -130.75,40.33 -128.09,34.8 -123.29,30.97 -117.3,29.6
  silkscreen extent -170,-200 170,120
USB-C-SMD_TYPEC-304-BCP16#2 [mil]
  oval 39.4x82.7 hole 23.6 slot 70.9 at 90 deg paste+0 mask+2: 13(-170.1,64.3) 14(170.1,64.3)
  oval 39.4x63 hole 23.6 slot 47.2 at 90 deg paste+0 mask+2: 15(-170.1,-100.3) 16(170.1,-100.3)
  rect 23.6x57.1 smd paste+0 mask+2: A1B12(-127,100.3) A4B9(-96.5,100.3) B1A12(126.8,100.3) B4A9(96.5,100.3)
  rect 11.8x57.1 smd paste+0 mask+2: A5(-49.2,100.3) A6(-9.8,100.3) A7(9.8,100.3) A8(49.2,100.3) B5(68.9,100.3) B6(29.5,100.3) B7(-29.5,100.3) B8(-68.9,100.3)
  Multi-Layer board cut-out: 103.5,43.4 104.87,37.41 108.7,32.61 114.23,29.95 120.37,29.95 125.9,32.61 129.73,37.41 131.1,43.4 131.1,43.4 129.73,49.39 125.9,54.19 120.37,56.85 114.23,56.85 108.7,54.19 104.87,49.39 103.5,43.4
  Multi-Layer board cut-out: -131.1,43.4 -129.73,37.41 -125.9,32.61 -120.37,29.95 -114.23,29.95 -108.7,32.61 -104.87,37.41 -103.5,43.4 -103.5,43.4 -104.87,49.39 -108.7,54.19 -114.23,56.85 -120.37,56.85 -125.9,54.19 -129.73,49.39 -131.1,43.4
  silkscreen extent -170,-200 170,120
"XTAL_SOP - FC-12M" [mm]
  rect 0.8x1.5 smd paste+0 mask+0.102: 1(0,0) 2(1.5,0)
  silkscreen extent -0.81,-0.99 2.29,0.94

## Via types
v1: diameter 19.68, hole 11.81, Top Layer to Bottom Layer, 688 vias
v2: diameter 19.69, hole 11.81, Top Layer to Bottom Layer, 42 vias
v3: diameter 19.7, hole 11.81, Top Layer to Bottom Layer, 30 vias
v4: diameter 23.62, hole 11.81, Top Layer to Bottom Layer, 17 vias
v5: diameter 27.56, hole 13.78, Top Layer to Bottom Layer, 15 vias
v6: diameter 27.56, hole 15.75, Top Layer to Bottom Layer, 2 vias

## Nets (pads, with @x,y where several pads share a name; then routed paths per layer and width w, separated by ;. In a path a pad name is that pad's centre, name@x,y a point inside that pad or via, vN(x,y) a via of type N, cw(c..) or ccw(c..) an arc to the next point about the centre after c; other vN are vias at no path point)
3V3: C20.2 CN2.1 CN7.1 D2.2 D4.1 D5.1 J4.2 J4.4 JP3.1 R3.1 R4.2 R13.2 R14.2 R15.2 U8.8 | length 9366.4
  Top Layer w10: R3.1@14494.08,5258.56 14495.08,5257.56 R4.2@14620.08,5257.56
  Top Layer w15: v2(14764.58,5061.56) 14764.92,5061.22 R15.2@14843.69,5061.21
  Top Layer w20: v6(13264.34,3609.01) 13221.01,3652.34 13221.01,4928.24 13303.83,5011.05 D5.1@13303.83,5090.56 ; v2(13782.58,3569.57) 13782.58,3693.57 13820.58,3731.57 14008.58,3731.57 14051.58,3774.57 v2(14051.58,4189.56) ; R4.2@14620.08,5257.56 14620.58,5258.06 JP3.1@14620.58,5357.55 14620.58,5399.36 D2.2@14690.58,5469.36 ; v1(14773.58,3836.57) 14773.86,3836.28 v3(15329.85,3836.28) v1(15683.86,3836.28) ; R15.2@14843.69,5061.21 14845.08,5059.84 R13.2@14845.08,4889.56 ; v3(15220.52,4357) C20.2@15335.52,4357 15335.52,4287.54 U8.8@15334.98,4287 ; J4.2@15683.86,3565.56 15683.88,3610.86 15702.58,3629.57 15863.58,3629.57 15883.88,3609.26 J4.4@15883.86,3565.56
  Bottom Layer w15: JP3.1@14620.58,5357.55 14620.58,5205.56 v2(14764.58,5061.56) ; v1@15683.58,3836.57 v1(15683.86,3836.28)
  Bottom Layer w20: v6(13264.34,3609.01) 13303.8,3569.57 v2(13782.58,3569.57) D4.1@13782.58,3414.2 13782.58,3387.68 13737.92,3343.01 13737.92,3229.01 13715.34,3206.45 CN7.1@13715.34,3166.01 ; JP3.1@14620.58,5357.55 14138.58,5357.56 14051.58,5270.56 v2(14051.58,4189.56) 14290.2,4189.56 CN2.1@14290.92,4188.85 14365.65,4263.56 14681.95,4263.56 14773.58,4171.94 v1(14773.58,3836.57) ; v3(15220.52,4357) 15220.52,3945.61 v3(15329.85,3836.28) ; J4.2@15683.86,3565.56 v1(15683.86,3836.28)
5V: CN1.1 CN2.2 CN5.1 CN7.2 D1.2 D3.1 D6.2 F1.1 J4.5 J7.2 | length 10668.6
  Top Layer w30: v6(13672.58,3239.57) 13672.58,3693.57 13750.58,3771.57 13962.58,3771.57 14000.58,3809.57 14000.58,5469.56 14044.89,5513.88 F1.1@14096.38,5513.88 ; 14000.58,4237.98 14003.3,4237.98 14036.13,4270.81 ; 14000.58,4304.48 14002.46,4304.48 14036.13,4270.81 ; CN2.2@14390.92,4188.85 14390.92,4249.22 14369.33,4270.81 14036.13,4270.81 ; J7.2@17098.88,4666.16 17191.97,4666.16 17285.58,4572.56 D1.2@17342.58,4572.56 D6.2@17342.58,4363.56
  Bottom Layer w15: D3.1@13676.62,3320.82 13676.58,3239.57 13664.58,3227.57 13664.58,3116.78 CN7.2@13715.34,3066.01 ; J4.5@15982.88,3565.56 15982.88,3498.26 16034.07,3447.07 16033.55,3115.86 16031.05,3113.36 ; 16032.05,3109.43 16032.05,3113.36
  Bottom Layer w30: CN2.2@14390.92,4188.85 14653.3,4188.85 14720.58,4121.56 14720.58,3184.66 14791.89,3113.36 16031.05,3113.36 16032.05,3113.36 16960.38,3113.36 17205.58,3358.57 17205.58,3473.09 ; J7.2@17098.88,4666.16 17204.25,4666.16 ; CN5.1@17412.22,3472.76 17205.9,3472.76 17205.58,3473.09 ; CN1.1@17413.22,5279.76 17310.77,5279.76 17239.58,5208.56 17239.58,4701.49 17204.25,4666.16 ; 17204.25,4666.16 17205.58,4664.84 17205.58,3473.09
$1N307: J9.2 U6.44 | length 154.6
  Top Layer w6: U6.44@13659.15,4534.23 13730.56,4534.23 J9.2@13789.34,4593.02
$1N334: LD4.1 RP1.5 | length 138.2
  Top Layer w6: LD4.1@13742.62,5041.36 13785.37,5041.36 v5(13786.58,5042.56)
  Bottom Layer w6: RP1.5@13713.41,4992.86 13736.88,4992.86 v5(13786.58,5042.56)
$1N335: LD3.1 RP1.6 | length 123.1
  Top Layer w6: LD3.1@13742.62,4971.76 13785.38,4971.76 v5(13786.58,4970.56)
  Bottom Layer w6: RP1.6@13713.41,4957.44 13773.44,4957.44 v5(13786.58,4970.56)
$1N336: LD2.1 RP1.7 | length 125.3
  Top Layer w6: LD2.1@13742.62,4902.16 13786.17,4902.16 v5(13786.58,4902.56)
  Bottom Layer w6: RP1.7@13713.41,4921.99 13767.15,4921.99 v5(13786.58,4902.56)
$1N337: LD1.1 RP1.8 | length 147.5
  Top Layer w6: LD1.1@13742.62,4832.56 v5(13790.58,4832.56)
  Bottom Layer w6: RP1.8@13713.41,4886.56 13736.58,4886.56 v5(13790.58,4832.56)
$1N361: C15.1 C16.1 C18.1 C19.1 F2.2 U5.1 U5.3 U7.1 U7.3 | length 730.4
  Top Layer w20: U5.3@13320.14,5404.9 13320.15,5483.86 C18.1@13321.15,5484.86 ; U5.1@13395.14,5404.9 C19.1@13395.15,5484.86 ; U7.3@13689.34,5406.9 C15.1@13689.34,5485.07 ; U7.1@13764.34,5406.9 C16.1@13764.34,5486.9
  Top Layer w30: C18.1@13321.15,5484.86 C19.1@13395.15,5484.86 ; F2.2@13617.56,5486.94 13689.58,5486.94 C16.1@13764.31,5486.94
  Bottom Layer w30: v5(13427.14,5404.91) 13616.74,5404.91 v5(13617.84,5406.02)
$1N396: R50.1 R51.1 U5.4 | length 160.1
  Top Layer w25: R51.1@13254.58,5230.06 13332.58,5230.06 R50.1@13335.08,5232.56 13320.15,5247.49 U5.4@13320.14,5304.9
$1N467: R43.1 R49.1 U7.4 | length 163.5
  Top Layer w20: R49.1@13616.92,5235.02 R43.1@13702.92,5235.02 13702.92,5266.02 13689.34,5279.6 U7.4@13689.34,5306.9
$2N290: C3.1 D2.1 R1.2 U2.5 | length 294.6
  Top Layer w20: U2.5@14417.58,5576.53 14513.92,5576.53 R1.2@14518.58,5571.87 C3.1@14590.58,5571.87 14638.07,5619.36 D2.1@14690.58,5619.36
$2N291: R1.1 R2.2 U2.4 | length 180.7
  Top Layer w20: U2.4@14417.58,5501.53 14462.55,5501.53 14477.89,5516.88 R1.1@14518.58,5516.87 R2.2@14518.08,5443.56
$2N326: LED1.1 R3.2 | length 110.5
  Top Layer w10: LED1.1@14328.62,5258.36 14328.83,5258.56 R3.2@14439.08,5258.56
$2N337: C1.1 C2.1 F1.2 U2.1 U2.3 | length 370.1
  Top Layer w6: U2.3@14317.58,5501.53 14346.55,5501.53 14360.58,5515.56 14360.58,5564.56 14348.6,5576.53 U2.1@14317.58,5576.53
  Top Layer w20: F1.2@14096.38,5574.88 14099.38,5571.88 C1.1@14172.58,5571.87 C2.1@14232.58,5571.87 14237.24,5576.53 U2.1@14317.58,5576.53
$2N360: B2.3 B2.4 R5.2 R7.1 | length 593.1
  Top Layer w10: B2.4@14883.61,3366.74 14886.02,3369.14 15196.06,3369.14 15246.16,3369.14 15270.58,3393.57 15270.58,3470.68 15273.45,3473.57 15269.08,3477.95 R5.2@15269.08,3529.57 R7.1@15269.08,3585.57
$2N488: LED3.1 R14.1 | length 90.1
  Top Layer w10: R14.1@14898.69,4975.21 14899.25,4975.77 LED3.1@14988.53,4975.77
$2N489: LED2.1 R13.1 | length 88.5
  Top Layer w10: R13.1@14900.08,4889.56 14900.3,4889.77 LED2.1@14988.53,4889.77
$2N490: LED4.1 R15.1 | length 90.4
  Top Layer w10: R15.1@14898.69,5061.21 14900.14,5059.77 LED4.1@14988.53,5059.77
$2N12409: JP4.1 R53.1 | length 303.4
  Top Layer w6: JP4.1@17103.58,4107.56 v1(17248.58,4107.56)
  Bottom Layer w6: v1(17248.58,4107.56) 17320.58,4107.56 17354.58,4141.56 R53.1@17392.92,4141.56
$2N12490: JP2.1 R54.1 | length 404.3
  Top Layer w6: JP2.1@17103.58,5072.56 17287.58,4888.56 v1(17287.58,4884.56)
  Bottom Layer w6: v1@17286.58,4885.56 v1(17287.58,4884.56) R54.1@17426.26,4884.56
$3N199: J6.5 | length 211.5
  Bottom Layer w6: 16880.58,3720.16 16881.06,3719.68 ; J6.5@16883.88,3565.57 16883.88,3716.86 16881.06,3719.68 ; 16936.58,3719.68 16881.06,3719.68
$3N200: J6.6 | length 225.1
  Bottom Layer w6: J6.6@16983.88,3565.57 17020.58,3602.26 17020.58,3719.16 17075.97,3719.16 17076.58,3718.57
$3N264: J3.3 | length 249.4
  Bottom Layer w6: 15864.58,5276.05 15923.93,5276.05 15924.58,5276.69 15923.88,5277.39 J3.3@15923.88,5465.56
$4N238: C25.2 R26.2 Y2.3 | length 181.2
  Top Layer w6: C25.2@15460.58,4683.56 15460.58,4616.72 Y2.3@15459.89,4616.03 15460.35,4615.56 R26.2@15573.08,4615.56
$4N239: C26.2 R27.2 Y2.1 | length 366.6
  Top Layer w6: C26.2@15283.58,4548.56 15372.73,4548.56 Y2.1@15373.26,4549.1 15373.26,4510.88 15394.58,4489.56 15501.08,4489.56 R27.2@15573.08,4561.56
